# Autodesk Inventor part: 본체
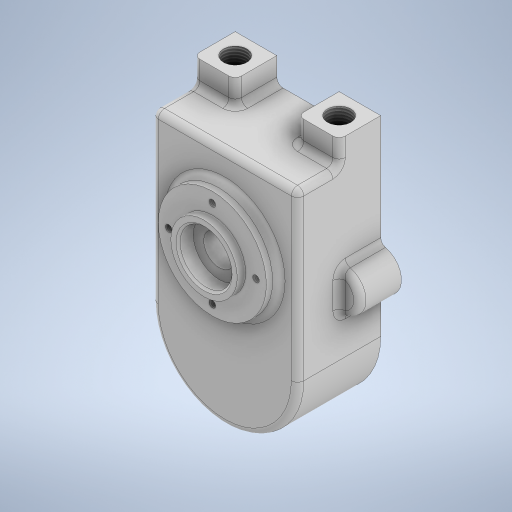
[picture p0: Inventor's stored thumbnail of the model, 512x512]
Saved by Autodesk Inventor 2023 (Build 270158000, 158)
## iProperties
Created: 2024-03
Part Number: 본체
Material: 일반
Document SubType Name: Modeling
Designer: asung
Density: 1 g/cm^3
Appearance: 기본값
Author: asung
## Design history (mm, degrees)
sketch "스케치1"
  geometry: L1 (-35, 40)-(35, 40); L2 (35, 40)-(35, -40); L3 (35, -40)-(-35, -40); L4 (-35, -40)-(-35, 40); L5 (-35, 40)-(35, -40); L6 (35, 40)-(-35, -40); A1 r 35 centre (0, -40) between (-35, -40) and (35, -40); 1 further point
  constraints: 12 end point, 2 midpoint, 2 parallel, 2 point on circle, 1 centre point, 1 horizontal, 1 perpendicular
  dimensions: "d0" = 70 distance of L2.end L3.end; "d1" = 80 distance of L1.end L2.end; "d2" = 35 radius of A1
extrude "돌출1" new body sketch "스케치1" distance "d3" = 40; taper "d4" = 0 deg
sketch "스케치2"
  geometry: L1 (-35, -40)-(-35, 40) reference; L2 (35, 40)-(35, -40) reference; L3 (-35, 40)-(35, 40) reference; L4 (0, 40)-(0, 0); L5 (0, 0)-(0, -40); L6 (-14, -11.314)-(-14, -28.686); L7 (14, -11.314)-(14, -28.686); A1 r 35 centre (0, -40) between (-35, -40) and (35, -40) reference; A2 r 18 centre (0, 0) between (14, -11.314) and (-14, -11.314); A3 r 18 centre (0, -40) between (-14, -28.686) and (14, -28.686); 3 further points
  constraints: 8 end point, 4 point on circle, 2 centre point, 2 coincident, 2 parallel, 2 vertical, 1 midpoint, 1 symmetric about line
  dimensions: "d12" = 40 distance of L4.start L4.end; "d13" = 36 diameter of A2; "d14" = 40 distance of L5.start L5.end (derived); "d15" = 36 diameter of A3; "d17" = 14 distance between parallel lines of L4 L7; "d18" = 28 distance between parallel lines of L6 L7; "d19" = 0 distance from line of point (14, -7) L7; "d20" = 0 distance from line of point (14, -35.376) L7; "d21" = 35.8469 distance of L5.end point (14, -7); "d22" = 14.74401 distance of L5.end point (14, -35.376)
extrude "돌출2" cut sketch "스케치2" distance "d23" = 20; taper "d24" = 0 deg
sketch "스케치3"
  geometry: L1 (70, -20)-(50, -20); L2 (50, -20)-(50, 0); L3 (50, 0)-(70, 0); L4 (70, 0)-(70, -20); L5 (70, 0)-(0, 0) reference; L6 (20, -20)-(0, -20); L7 (0, -20)-(0, 0); L8 (0, 0)-(20, 0); L9 (20, 0)-(20, -20); 3 further points
  constraints: 16 end point, 4 parallel, 2 horizontal, 2 perpendicular, 1 coincident, 1 midpoint, 1 point on line
  dimensions: "d25" = 20 distance of L2.end L3.end; "d26" = 20 distance of L1.end L2.end; "d27" = 20 distance of L5.end L8.end; "d28" = 20 distance of L5.end L6.end
extrude "돌출3" join sketch "스케치3" distance "d29" = 12; taper "d30" = 0 deg
fillet "모깎기1" dims "d31" = 3
fillet "모깎기2" dims "d32" = 3
sketch "스케치4"
  geometry: L1 (-14, -28.686)-(-14, -11.314) reference; L2 (14, -11.314)-(14, -28.686) reference; L3 (-35, -40)-(-35, 52) reference; L4 (35, -40)-(35, 52) reference; L5 (15, 52)-(35, 52) reference; L6 (15, 43)-(15, 52) reference; L7 (-12, 40)-(12, 40) reference; L8 (-15, 43)-(-15, 52) reference; L9 (-35, 52)-(-15, 52) reference; L10 (-35, 52)-(-35, -11.5); L11 (0, 40)-(0, 29.195); A1 r 18 centre (0, -40) between (-14, -28.686) and (14, -28.686) reference; A2 r 18 centre (0, 0) between (14, -11.314) and (-14, -11.314) reference; A3 r 35 centre (0, -40) between (-35, -40) and (35, -40) reference; A4 r 3 centre (12, 43) between (12, 40) and (15, 43) reference; A5 r 3 centre (-12, 43) between (-15, 43) and (-12, 40) reference; A6 r 10 centre (-35, -11.5) between (-35, -1.5) and (-35, -21.5); A7 r 10 centre (35, -11.5) between (35, -21.5) and (35, -1.5); 4 further points
  constraints: 4 end point, 4 point on circle, 3 point on line, 3 symmetric about line, 2 centre point, 1 coincident, 1 midpoint, 1 vertical, 1 other
  dimensions: "d33" = 63.5 distance of L3.end L10.end; "d34" = 10 radius of A6
extrude "돌출4" join sketch "스케치4" distance "d35" = 20; taper "d36" = 0 deg
fillet "모깎기3" dims "d37" = 3
fillet "모깎기4" dims "d38" = 3
sketch "스케치5"
  geometry: L1 (-14, -28.686)-(-14, -11.314) reference; L2 (14, -11.314)-(14, -28.686) reference; L3 (-35, -40)-(-35, -24.149) reference; L4 (35, -40)-(35, -24.149) reference; L5 (35, 1.149)-(35, 52) reference; L6 (15, 52)-(35, 52) reference; L7 (15, 43)-(15, 52) reference; L8 (-12, 40)-(12, 40) reference; L9 (-15, 43)-(-15, 52) reference; L10 (-35, 52)-(-15, 52) reference; L11 (-35, 1.149)-(-35, 52) reference; L12 (0, -40)-(0, -66); A1 r 18 centre (0, -40) between (-14, -28.686) and (14, -28.686) reference; A2 r 18 centre (0, 0) between (14, -11.314) and (-14, -11.314) reference; A3 r 35 centre (0, -40) between (-35, -40) and (35, -40) reference; A4 r 3 centre (38, -24.149) between (37.308, -21.23) and (35, -24.149) reference; A5 r 10 centre (35, -11.5) between (37.308, -21.23) and (37.308, -1.77) reference; A6 r 3 centre (38, 1.149) between (35, 1.149) and (37.308, -1.77) reference; A7 r 3 centre (12, 43) between (12, 40) and (15, 43) reference; A8 r 3 centre (-12, 43) between (-15, 43) and (-12, 40) reference; A9 r 3 centre (-38, 1.149) between (-37.308, -1.77) and (-35, 1.149) reference; A10 r 10 centre (-35, -11.5) between (-37.308, -1.77) and (-37.308, -21.23) reference; A11 r 3 centre (-38, -24.149) between (-35, -24.149) and (-37.308, -21.23) reference; 3 further points
  constraints: 2 end point, 1 coincident, 1 vertical
  dimensions: "d54" = 26 distance of L12.start L12.end
  node "투영된 루프3"
hole "구멍2" sketch "스케치5" diameter "d47" = 4.134; stored, may be unused: countersink angle "d51" = 90 deg, drill point angle "d53" = 118 deg; dims "d48" = 10, "d49" = 4, "d50" = 2, "d52" = 12
sketch "스케치7"
  geometry: C1 r 26 at (0, 0); 1 further point
  constraints: 1 centre point, 1 coincident
  dimensions: "d55" = 52 diameter of C1
extrude "돌출5" join sketch "스케치7" distance "d56" = 6; taper "d57" = 0 deg
sketch "스케치8"
  geometry: C1 r 16 at (0, 0); 1 further point
  constraints: 1 centre point, 1 coincident
  dimensions: "d58" = 32 diameter of C1
extrude "돌출6" join sketch "스케치8" distance "d59" = 4; taper "d60" = 0 deg
fillet "모깎기5" dims "d61" = 3
sketch "스케치9"
  geometry: C1 r 16 at (0, 0) reference; 2 further points
  constraints: 1 coincident
hole "구멍3" sketch "스케치9" at (0, 0) diameter "d62" = 15; stored, may be unused: countersink angle "d66" = 90 deg, drill point angle "d68" = 0 deg; dims "d63" = 10, "d64" = 25, "d65" = 7.3, "d67" = 20
sketch "스케치10"
  geometry: A1 r 18 centre (0, -40) between (-14, -28.686) and (14, -28.686) reference; 2 further points
  constraints: 1 coincident
hole "구멍4" sketch "스케치10" at (0, -40) diameter "d69" = 20; stored, may be unused: countersink angle "d73" = 90 deg, drill point angle "d75" = 120 deg; dims "d70" = 6, "d71" = 20, "d72" = 20, "d74" = 10
chamfer "모따기1" distance "d76" = 1; stored, may be unused: second distance "d77" = 2, angle "d78" = 45 deg
sketch "스케치11" dims "d79" = 42
  geometry: 3 further points
  constraints: 1 coincident, 1 vertical alignment, 2 other
hole "구멍5" sketch "스케치11" at (0, 21) diameter "d80" = 3.242; stored, may be unused: countersink angle "d84" = 90 deg, drill point angle "d86" = 120 deg; dims "d81" = 8, "d82" = 4, "d83" = 2, "d85" = 10
sketch "스케치12"
  geometry: A1 r 18 centre (0, 0) between (14, -11.314) and (-14, -11.314) reference; 2 further points
  constraints: 1 coincident
hole "구멍6" sketch "스케치12" at (0, 0) diameter "d90" = 20; stored, may be unused: countersink angle "d94" = 90 deg, drill point angle "d96" = 0 deg; dims "d91" = 6, "d92" = 25, "d93" = 7.3, "d95" = 10
sketch "스케치13"
  geometry: 1 further point
sketch "스케치14"
  geometry: L1 (0, 0)-(0, 26); 1 further point
  constraints: 2 end point, 1 coincident, 1 vertical
  dimensions: "d97" = 26 distance of L1.start L1.end
hole "구멍7" sketch "스케치14" at (0, 26) diameter "d98" = 4.134; stored, may be unused: countersink angle "d102" = 90 deg, drill point angle "d104" = 118 deg; dims "d99" = 10, "d100" = 25, "d101" = 7.3, "d103" = 12
sketch "스케치16"
  geometry: L1 (70, 0)-(50, 0) reference; L2 (60, 0)-(60, -10); 2 further points
  constraints: 2 end point, 1 coincident, 1 midpoint, 1 vertical
  dimensions: "d105" = 10 distance of L2.start L2.end
hole "구멍8" sketch "스케치16" at (60, -10) diameter "d106" = 10.5; stored, may be unused: countersink angle "d112" = 90 deg, drill point angle "d114" = 118 deg; dims "d107" = 11, "d108" = 0.62479, "d109" = 10.589, "d110" = 4, "d111" = 2, "d113" = 16
chamfer "모따기2" distance "d115" = 1; stored, may be unused: second distance "d116" = 2, angle "d117" = 45 deg
chamfer "모따기3" distance "d118" = 1; stored, may be unused: second distance "d119" = 2, angle "d120" = 45 deg
feature "ſ耀Ɓ耀ƃ耀ƅ耀Ƈ耀Ɖ耀Ƌ耀ƍ耀" dims "d0" = 70, "d1" = 80, "d2" = 35, "d3" = 40, "d4" = 0, "d6" = 36, "d8" = 36, "d12" = 40, "d13" = 36, "d14" = 40 (derived), "d15" = 36, "d17" = 14, "d18" = 28, "d19" = 0, "d20" = 0, "d21" = 35.8469, "d22" = 14.74401, "d23" = 20, "d24" = 0, "d25" = 20, "d26" = 20, "d27" = 20, "d28" = 20, "d29" = 12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
node "솔리드1"
mirror "미러1"
pattern_circular "원형 패턴1" dims angle "d88" = 360 deg
mirror "미러2"
node "투영된 루프1"
node "투영된 루프2"
feature "A9D066F2-1C7D-4E18-AEED-F7BC21143FA4" dims "d62" = 15, "d63" = 10, "d64" = 25, "d65" = 7.3, "d66" = 90 deg, "d67" = 20, "d68" = 0
